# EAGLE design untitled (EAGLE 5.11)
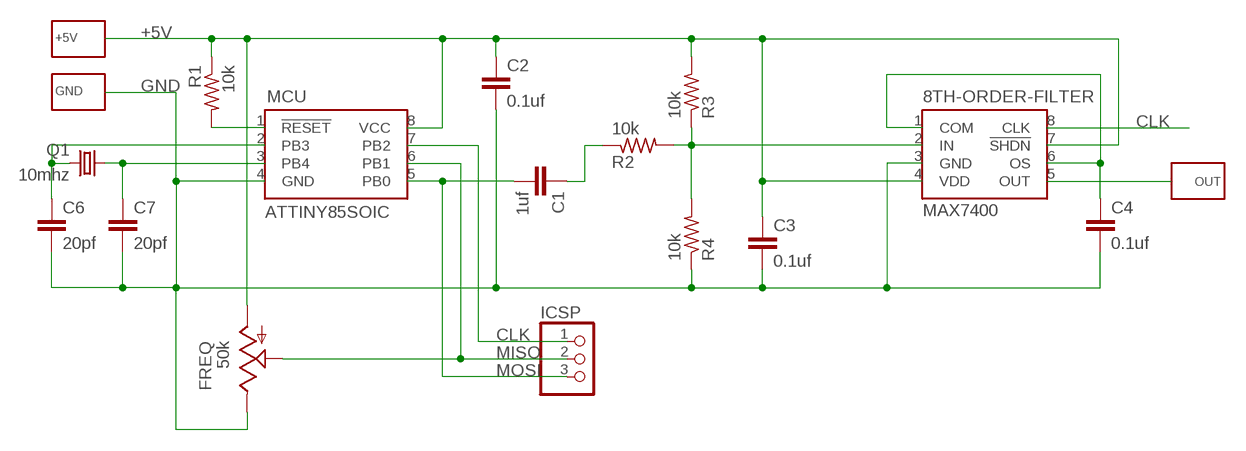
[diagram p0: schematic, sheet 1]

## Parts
8TH-ORDER-FILTER  MAX7400  [8SOIC]
+5V  WIREPAD-SMD-NO-VALUE  [WIREPAD-SMD]
C1  1uf  C-EUC0805  [C0805]
C2  0.1uf  C-EUC0805  [C0805]
C3  0.1uf  C-EUC0805  [C0805]
C4  0.1uf  C-EUC0805  [C0805]
C6  20pf  C-EU050-024X044  [C050-024X044]
C7  20pf  C-EU050-024X044  [C050-024X044]
FREQ  50k  POT-TRIM-0.35IN  [POT-TRIM-0.35IN]
GND  WIREPAD-SMD-NO-VALUE  [WIREPAD-SMD]
ICSP  PINHD-1X3  [1X03]
MCU  ATTINY85SOIC  [8SOIC]
OUT  WIREPAD-SMD-NO-VALUE  [WIREPAD-SMD]
Q1  10mhz  CRYSTALHC49S  [HC49/S]
R1  10k  R-US_R0805  [R0805]
R2  10k  R-US_R0805  [R0805]
R3  10k  R-US_R0805  [R0805]
R4  10k  R-US_R0805  [R0805]

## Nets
+5V: 8TH-ORDER-FILTER.4(VDD) 8TH-ORDER-FILTER.7(!SHDN) +5V.1(P) C2.1 C3.1 FREQ.1(A) MCU.8(VCC) R1.1 R3.2
CLK: 8TH-ORDER-FILTER.8(CLK) ICSP.1 MCU.7(PB2)
GND: 8TH-ORDER-FILTER.3(GND) C2.2 C3.2 C4.2 C6.2 C7.2 FREQ.3(E) GND.1(P) MCU.4(GND) R4.1
MISO: FREQ.2(S) ICSP.2 MCU.6(PB1)
MOSI: C1.2 ICSP.3 MCU.5(PB0)
N$1: C6.1 MCU.2(PB3) Q1.2
N$2: MCU.1(!RESET) R1.2
N$3: 8TH-ORDER-FILTER.1(COM) 8TH-ORDER-FILTER.6(OS) C4.1
N$4: C7.1 MCU.3(PB4) Q1.1
N$5: 8TH-ORDER-FILTER.2(IN) R2.2 R3.1 R4.2
N$7: C1.1 R2.1
OUT: 8TH-ORDER-FILTER.5(OUT) OUT.1(P)

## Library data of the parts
8TH-ORDER-FILTER = trl:MAX7400
+5V GND OUT = trl:WIREPAD-SMD-NO-VALUE
C1-C4 C6 C7 = resistor:C-EU: CAPACITOR, European symbol
FREQ = trl:POT-TRIM-0.35IN
ICSP = pinhead:PINHD-1X3: PIN HEADER
MCU = trl:ATTINY85
Q1 = crystal:CRYSTAL: CRYSTAL; OC_FARNELL: 1667008; OC_NEWARK: unknown
R1-R4 = resistor:R-US_: RESISTOR, American symbol

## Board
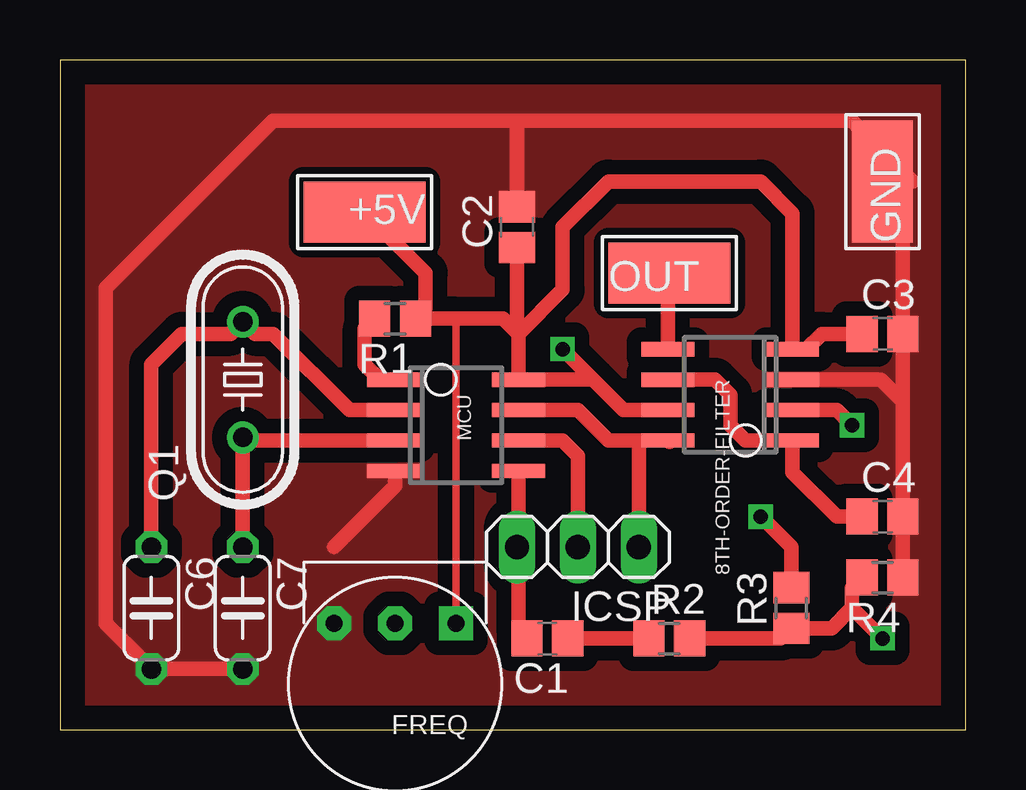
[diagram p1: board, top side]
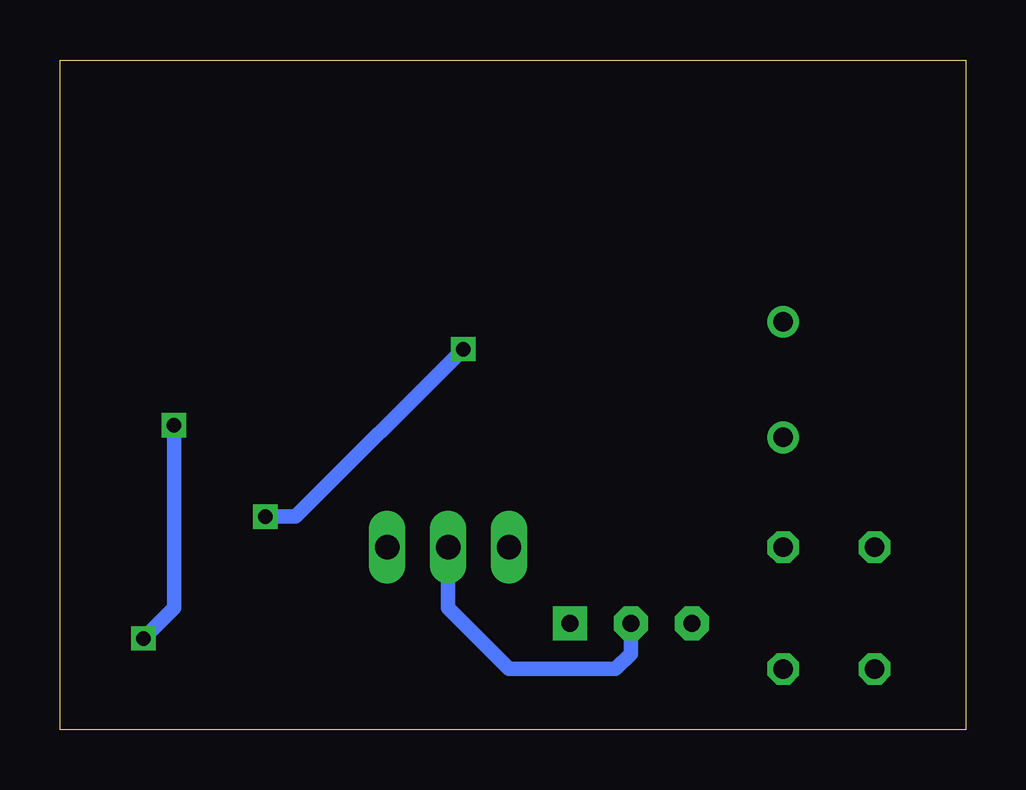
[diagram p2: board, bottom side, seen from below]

Size 37.77 x 27.93 mm. Coordinates in mm from the lower left corner, seen from the top.
Outline: 0,0 37.77,0 37.77,27.93 0,27.93 0,0
Copper layers (1*16): Top 0.035mm / dielectric 1.5mm / Bottom 0.035mm
Design rules "default": minimum track width 10mil, minimum drill 0.6mm, track to track 8mil, track to pad 8mil, pad to pad 8mil, via to via 8mil, smd to smd 8mil, copper to edge 40mil, drill to drill 8mil, minimum pad ring 10mil, minimum via ring 8mil, stop-mask expansion 4mil, vias tented up to drill 0mil, thermal gap 10mil

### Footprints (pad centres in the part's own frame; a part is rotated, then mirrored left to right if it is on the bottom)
8SOIC = smd 0.6 x 2.2: 1 -1.905,-2.6; 2 -0.635,-2.6; 3 0.635,-2.6; 4 1.905,-2.6; 5 1.905,2.6; 6 0.635,2.6; 7 -0.635,2.6; 8 -1.905,2.6
WIREPAD-SMD = smd 2.54 x 5.08: 1 0,0
C0805 = smd 1.3 x 1.5: 1 -0.85,0; 2 0.85,0
C050-024X044 = drill 0.813 octagon: 1 -2.54,0; 2 2.54,0
POT-TRIM-0.35IN = drill 0.7 pad 1.422 square: 1 -2.54,-3.81 | drill 0.7 pad 1.422 octagon: 2 0,-3.81; 3 2.54,-3.81
1X03 = drill 1.016 long: 1 -2.54,0; 2 0,0; 3 2.54,0
HC49/S = drill 0.813 round: 1 -2.413,0; 2 2.413,0
R0805 = smd 1.3 x 1.5: 1 -0.85,0; 2 0.85,0

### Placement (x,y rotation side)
8TH-ORDER-FILTER  27.94,13.97 90 top
+5V  12.7,21.59 90 top
C1  20.32,3.81 180 top
C2  19.05,20.95 90 top
C3  34.29,16.51 0 top
C4  34.29,8.89 0 top
C6  3.81,5.08 270 top
C7  7.62,5.08 270 top
FREQ  13.97,0.64 180 top
GND  34.29,22.86 0 top
ICSP  21.59,7.62 180 top
MCU  16.51,12.7 270 top
OUT  25.4,19.05 270 top
Q1  7.62,14.61 90 top
R1  13.97,17.14 180 top
R2  25.4,3.81 0 top
R3  30.48,5.08 90 top
R4  34.29,6.35 180 top

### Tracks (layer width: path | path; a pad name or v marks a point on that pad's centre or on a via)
+5V  (via drill 0.6)
  Top 0.305: FREQ.1 16.51,17.14
  Top 0.61: 19.11,16.51 MCU.8 22.23,14.61 | 8TH-ORDER-FILTER.7 23.5,13.34 22.23,14.61 | 19.05,16.57 18.48,17.14 16.51,17.14 R1.1 15.24,17.57 15.24,19.05 +5V.1 | 19.05,16.57 C2.1 | 19.05,16.57 19.11,16.51 | 19.11,16.51 20.95,18.36 20.95,20.95 22.86,22.86 29.21,22.86 30.54,21.53 8TH-ORDER-FILTER.4 31.11,15.88 31.75,16.51 C3.1 | R3.2 30.48,7.62 v29.21,8.89 | 22.23,14.61 v20.95,15.88
  Bottom 0.61: v29.21,8.89 27.94,8.89 v20.95,15.88
CLK
  Top 0.61: MCU.7 21.59,13.34 22.86,12.06 24.13,12.06 | 24.13,12.06 8TH-ORDER-FILTER.8 25.4,12.01 | ICSP.1 24.13,12.06
GND
  Top 0.61: 8TH-ORDER-FILTER.3 34.08,14.61 34.24,14.59 35.14,13.69 | R4.1 C4.2 35.14,13.69 | 35.14,13.69 C3.2 35.14,22.01 GND.1 35.56,22.86 33.02,25.4 19.05,25.4 | 19.05,25.4 8.89,25.4 1.91,18.41 1.91,4.45 C6.2 C7.2 | 19.05,25.4 C2.2 | MCU.4 13.97,10.73 13.97,10.16 11.43,7.62
  pour Top (isolate 0.61, no thermals): 0,27.94 38.1,27.94 38.1,0 0,0
MISO
  Top 0.61: MCU.6 20.95,12.06 21.59,11.43 ICSP.2
  Bottom 0.61: ICSP.2 21.59,5.08 19.05,2.54 14.61,2.54 13.97,3.17 FREQ.2
MOSI
  Top 0.61: 19.11,7.56 MCU.5 | 19.11,7.56 ICSP.3 | 19.11,7.56 19.11,4.17 C1.2
N$1
  Top 0.61: C6.1 3.81,15.24 5.08,16.51 7.11,16.51 Q1.2 8.13,16.51 8.89,16.51 12.06,13.34 MCU.2
N$2
  Top 0.61: MCU.1 13.34,14.61 12.7,15.24 12.7,16.73 R1.2
N$3
  Top 0.61: 8TH-ORDER-FILTER.6 27.3,14.61 27.94,13.97 27.94,12.7 28.57,12.06 8TH-ORDER-FILTER.1 30.54,10.73 32.38,8.89 C4.1
N$4
  Top 0.61: MCU.3 7.75,12.06 Q1.1 C7.1
N$5  (via drill 0.6)
  Top 0.61: R2.2 30.06,3.81 R3.1 32.17,4.23 33.02,5.08 | 33.02,5.08 33.02,5.93 R4.2 | 8TH-ORDER-FILTER.2 32.38,13.34 v33.02,12.7 | 33.02,5.08 v34.29,3.81
  Bottom 0.61: v33.02,12.7 33.02,5.08 v34.29,3.81
N$7
  Top 0.61: C1.1 R2.1
OUT
  Top 0.61: 8TH-ORDER-FILTER.5 25.34,18.99 OUT.1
